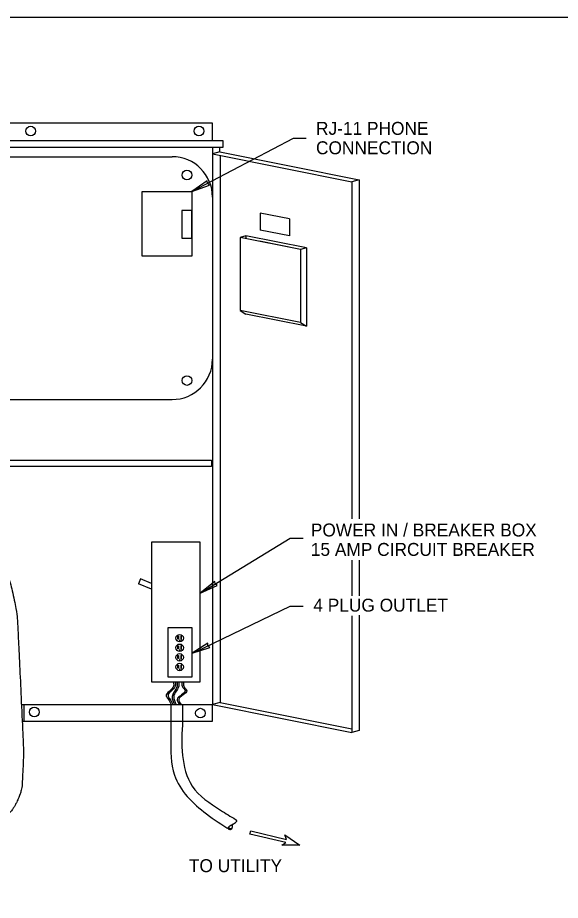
# Model space of a CAD drawing. Extents: x 99862 to 103151, y 100000 to 108076.
# Drawn here: x 100456 to 101127, y 106985 to 108076 of the extents above; entities that cross this region are included whole.
import ezdxf

# ---------------------------------------------------------------- set-up
doc = ezdxf.new("R2010")
doc.units = 0
for name, color, linetype in [('Level 1', 7, 'Continuous'), ('Level 15', 7, 'Continuous'), ('Level 20', 7, 'Continuous'), ('Level 28', 7, 'Continuous'), ('Level 30', 7, 'Continuous'), ('Level 33', 7, 'Continuous'), ('Level 34', 7, 'Continuous'), ('Level 46', 7, 'Continuous'), ('Level 50', 7, 'Continuous'), ('Level 7', 7, 'Continuous')]:
    doc.layers.add(name, color=color, linetype=linetype)

msp = doc.modelspace()

# ---------------------------------------------------------------- linework, layer by layer
at = {"layer": 'Level 1'}
msp.add_lwpolyline([(99862, 105999.5), (103151, 105999.5), (103151, 108075.5), (99862, 108075.5)], close=True, dxfattribs=at)
msp.add_lwpolyline([(99862, 105999.5), (103151, 105999.5), (103151, 108075.5), (99862, 108075.5)], close=True, dxfattribs=at)
at = {"layer": 'Level 15'}
for p, q in [((100671.8, 107860.7), (100797.3, 107926.7)), ((100797.3, 107926.7), (100813.3, 107926.7)), ((100682.2, 107364.4), (100793.5, 107432.3)), ((100793.5, 107432.3), (100809.5, 107432.3)), ((100674.5, 107291.2), (100793.5, 107348.2)), ((100793.5, 107348.2), (100809.5, 107348.2))]:
    msp.add_line(p, q, dxfattribs=at)
for points in [[(100671.8, 107860.7), (100693.4, 107868.7), (100691.1, 107870.8), (100690.6, 107874)], [(100682.2, 107364.4), (100703.2, 107373.8), (100700.7, 107375.8), (100700.1, 107378.9)], [(100672, 107290.3), (100694, 107297.3), (100691.7, 107299.6), (100691.4, 107302.7)]]:
    msp.add_lwpolyline(points, close=True, dxfattribs=at)
at = {"layer": 'Level 28'}
msp.add_open_spline([(100264, 107670.4), (100261.9, 107670.4), (100258.7, 107670.4), (100255, 107670.4), (100253.2, 107670.4), (100252.4, 107670.4), (100251.9, 107670.4), (100251.9, 107670.4), (100251.3, 107670.4), (100250.8, 107670.3), (100248.9, 107669.6), (100247.7, 107669), (100244.9, 107667.3), (100243.2, 107666.2), (100239.5, 107663.6), (100238.1, 107662.7), (100234.2, 107659.6), (100232.3, 107657.6), (100230.4, 107654.8), (100230, 107654.2), (100229.3, 107653), (100229, 107652.4), (100228.3, 107650.8), (100227.9, 107649.6), (100227.1, 107645.7), (100227, 107642.7), (100227.8, 107636.3), (100228.6, 107632.9), (100230, 107629), (100230.4, 107628), (100231.1, 107626.2), (100231.5, 107625.3), (100232.6, 107622.6), (100233.3, 107620.8), (100235.6, 107615.9), (100237.3, 107612.9), (100240.1, 107609), (100241.1, 107607.8), (100242.7, 107606.1), (100243.3, 107605.6), (100244.1, 107604.8), (100244.6, 107604.4), (100245.3, 107603.8), (100245.7, 107603.4), (100252.1, 107597.9), (100258.5, 107593.3), (100278.8, 107580.2), (100293.7, 107572.5), (100312, 107560.2), (100315.6, 107557.6), (100320.1, 107554.1), (100321, 107553.4), (100322.8, 107551.9), (100323.6, 107551.3), (100326, 107549.3), (100327.6, 107548), (100335.8, 107541.3), (100342.3, 107535.8), (100361.7, 107519.2), (100374.3, 107507.4), (100389.3, 107491), (100392.3, 107487.6), (100398.1, 107480.6), (100400.9, 107476.9), (100409, 107465.9), (100413.8, 107458.3), (100422.5, 107442.8), (100426.3, 107434.8), (100433.2, 107418.5), (100436.2, 107410), (100444.5, 107385.4), (100449.7, 107368.7), (100454.7, 107342.5), (100455.9, 107333.6), (100456.5, 107322.3), (100456.6, 107320.3), (100456.8, 107316.1), (100457.1, 107309.8), (100459, 107269.8), (100460.8, 107231.9), (100463.1, 107181.5), (100463.9, 107164.6), (100461.9, 107128.9), (100461.9, 107128.1), (100461.6, 107124.1), (100460.9, 107121.1), (100459.3, 107115.7), (100458.3, 107113.3), (100456.3, 107108.7), (100455.4, 107106.6), (100453.1, 107102.1), (100451.7, 107099.7), (100449.1, 107096), (100448.1, 107094.8), (100446.5, 107093.1), (100446.2, 107092.8), (100445.5, 107092), (100425.6, 107067), (100402.2, 107042), (100378.5, 107016.5)], degree=3, dxfattribs=at)
at = {"layer": 'Level 30'}
msp.add_lwpolyline([(100721.6, 107074.1), (100721.2, 107073.5)], dxfattribs=at)
for points in [[(100720.9, 107073), (100720.8, 107072.8), (100720.6, 107072.5), (100720.2, 107072.3), (100719.7, 107072.1), (100719.3, 107072), (100719, 107072), (100718.6, 107072.1), (100718.3, 107072.2), (100718, 107072.3), (100717.7, 107072.5), (100717.4, 107072.7), (100717.2, 107073), (100717.1, 107073.3), (100717, 107073.7), (100716.9, 107074.1), (100717, 107074.5), (100717.2, 107075), (100717.6, 107075.5), (100718, 107076), (100718.5, 107076.5), (100719.1, 107076.9), (100719.7, 107077.3), (100720.3, 107077.7), (100720.9, 107078), (100721.5, 107078.4), (100722.1, 107078.7), (100722.7, 107079), (100723.3, 107079.3), (100723.9, 107079.7), (100724.5, 107080), (100725.1, 107080.4), (100725.7, 107080.7), (100726.2, 107081.2), (100726.4, 107081.5), (100726.5, 107081.7)], [(100725.8, 107084.7), (100725.8, 107084.7), (100726, 107084.6), (100726.2, 107084.4), (100726.4, 107084.1), (100726.6, 107083.8), (100726.8, 107083.5), (100726.9, 107083.1), (100726.9, 107082.7), (100726.8, 107082.2), (100726.7, 107081.8), (100726.5, 107081.7)], [(100721.2, 107073.5), (100720.9, 107073.3), (100720.7, 107073.2), (100720.4, 107073.1), (100720, 107073.1), (100719.7, 107073.1), (100719.3, 107073.2), (100719, 107073.3), (100718.7, 107073.5), (100718.4, 107073.6), (100718.2, 107073.9), (100717.9, 107074.1), (100717.8, 107074.4), (100717.6, 107074.7), (100717.6, 107075), (100717.6, 107075.4), (100717.7, 107075.6), (100717.7, 107075.7)], [(100721.6, 107074.1), (100721.7, 107074.2), (100721.7, 107074.4), (100721.8, 107074.6), (100721.8, 107074.6)], [(100721.9, 107076.9), (100721.9, 107077.1), (100721.9, 107077.4), (100721.8, 107078), (100721.8, 107078.4), (100721.7, 107078.6), (100721.7, 107078.6)], [(100721.8, 107074.6), (100721.8, 107074.6), (100721.9, 107074.8), (100721.9, 107075.2), (100721.9, 107075.6), (100721.9, 107075.8), (100721.9, 107075.8)], [(100721.9, 107075.8), (100722, 107075.8), (100722, 107076), (100722, 107076.4), (100721.9, 107076.8), (100721.9, 107077), (100721.9, 107077)]]:
    msp.add_open_spline(points, degree=3, dxfattribs=at)
at = {"layer": 'Level 33'}
for p, q in [((100464.1, 107226.7), (100464.1, 107206.2)), ((100645.8, 107226.7), (100645.8, 107206.3)), ((100660.3, 107226.7), (100660.3, 107206.3))]:
    msp.add_line(p, q, dxfattribs=at)
at = {"layer": 'Level 34'}
msp.add_lwpolyline([(100721.2, 107073.5), (100720.9, 107073)], dxfattribs=at)
for points in [[(100649.1, 107254.6), (100649.1, 107249.5), (100640.2, 107237.1), (100642.9, 107233.1), (100645.8, 107226.9)], [(100651.2, 107254.6), (100651.2, 107249.5), (100642.3, 107237.1), (100645, 107233.1), (100647.9, 107226.9)], [(100653.6, 107254.6), (100653.6, 107249.5), (100649.4, 107241.8), (100647.4, 107236.6), (100650.4, 107226.9)], [(100655.6, 107254.6), (100655.6, 107249.5), (100651.4, 107241.8), (100649.4, 107236.6), (100652.4, 107226.9)], [(100659.7, 107254.6), (100659.7, 107249.5), (100663.5, 107243.7), (100653.5, 107233.1), (100656.5, 107226.9)], [(100661.7, 107254.6), (100661.7, 107249.5), (100665.5, 107243.7), (100655.5, 107233.1), (100658.5, 107226.9)], [(100645.8, 107206.3), (100645.8, 107184.9), (100650.2, 107139.6), (100689.9, 107091.5), (100718.6, 107072.2)], [(100660.3, 107206.3), (100660.3, 107163.8), (100672.2, 107126), (100707.3, 107096.2), (100725.8, 107084.7)]]:
    msp.add_spline(points, degree=3, dxfattribs=at)
at = {"layer": 'Level 46'}
msp.add_lwpolyline([(100743.5, 107066.7), (100744.6, 107070.5), (100788.9, 107060.1), (100786.9, 107065.6), (100805.4, 107053), (100783, 107052.9), (100787.8, 107056.3), (100743.5, 107066.7)], dxfattribs=at)
at = {"layer": 'Level 50'}
for p, q in [((100626.7, 107945), (100239.6, 107945)), ((100697.2, 107945), (100626.7, 107945)), ((100697.2, 107923.2), (100697.2, 107945)), ((100697.3, 107915.3), (100697.3, 107226.7)), ((100706.4, 107909.6), (100697.3, 107907.2)), ((100706.4, 107909.6), (100706.4, 107915.3)), ((100706.4, 107909.6), (100878.6, 107875.1)), ((100289.4, 107903.7), (100647.3, 107903.7)), ((100697.3, 107907.2), (100869.5, 107872.7)), ((100706.9, 107905.3), (100706.9, 107229.2)), ((100878.6, 107875.1), (100869.5, 107872.7)), ((100878.6, 107875.1), (100878.6, 107456.1)), ((100869.5, 107872.7), (100869.5, 107456.1)), ((100792.5, 107826.7), (100756.2, 107834)), ((100756.2, 107834), (100756.2, 107813)), ((100792.5, 107826.7), (100792.5, 107805.8)), ((100792.5, 107805.8), (100756.2, 107813)), ((100738.6, 107805.7), (100731.4, 107803.8)), ((100806.2, 107789), (100731.4, 107803.8)), ((100731.4, 107803.8), (100731.4, 107713.7)), ((100738.6, 107805.7), (100738.6, 107802.4)), ((100813.5, 107790.9), (100738.6, 107805.7)), ((100806.2, 107789), (100755.3, 107799.1)), ((100813.5, 107790.9), (100806.2, 107789)), ((100806.2, 107789), (100806.2, 107698.9)), ((100813.5, 107790.9), (100813.5, 107694.3)), ((100813.5, 107785.7), (100813.5, 107698.4)), ((100806.2, 107698.9), (100731.4, 107713.7)), ((100731.4, 107713.7), (100738.6, 107709.1)), ((100813.5, 107694.3), (100738.6, 107709.1)), ((100806.2, 107698.9), (100813.5, 107694.3)), ((100326.2, 107603.6), (100647.3, 107603.6)), ((100869.5, 107405.1), (100869.5, 107361.2)), ((100878.6, 107405.1), (100878.6, 107361.2)), ((100608.3, 107382.2), (100605.6, 107376)), ((100621.7, 107369.1), (100605.6, 107376)), ((100622, 107376.4), (100608.3, 107382.2)), ((100869.5, 107336.3), (100869.5, 107192.2)), ((100878.6, 107337), (100878.6, 107194.6)), ((100460.7, 107226.7), (100553.2, 107226.7)), ((100551.2, 107226.7), (100659.8, 107226.7)), ((100659.7, 107226.7), (100697.3, 107226.7)), ((100706.9, 107229.2), (100697.3, 107226.7)), ((100697.3, 107226.7), (100869.5, 107192.2)), ((100697.3, 107206.2), (100697.3, 107226.7)), ((100706.9, 107229.2), (100869.5, 107196.6)), ((100461.8, 107206.2), (100552.9, 107206.2)), ((100551.2, 107206.2), (100659.8, 107206.2)), ((100659.9, 107206.2), (100697.3, 107206.2)), ((100878.6, 107194.6), (100869.5, 107192.2))]:
    msp.add_line(p, q, dxfattribs=at)
for points in [[(100710.6, 107915.3), (100710.6, 107923.2), (100226.3, 107923.2), (100226.3, 107915.3)], [(100610.4, 107860.7), (100671.8, 107860.7), (100671.8, 107780.6), (100610.4, 107780.6)], [(100671.9, 107837.4), (100659.3, 107837.4), (100659.3, 107803.1), (100671.9, 107803.1)], [(100622, 107254.6), (100682.2, 107254.6), (100682.2, 107427.3), (100622, 107427.3)]]:
    msp.add_lwpolyline(points, close=True, dxfattribs=at)
msp.add_lwpolyline([(100436.1, 107528.7), (100696, 107528.7), (100696, 107520.7), (100437, 107520.7)], dxfattribs=at)
for centre in [(100472.5, 107935.3), (100680.6, 107935.4), (100665.7, 107881), (100665.7, 107627.1), (100476.9, 107217.4), (100682.4, 107216.1)]:
    msp.add_circle(centre, 5.97, dxfattribs=at)
for centre, start, end in [((100647.3, 107853.7), 0, 90), ((100647.3, 107653.6), 270, 0)]:
    msp.add_arc(centre, 50, start, end, dxfattribs=at)
at = {"layer": 'Level 7'}
for p, q in [((100656.3, 107305.8), (100656.3, 107305)), ((100657, 107305), (100656.3, 107305)), ((100657, 107305.8), (100657, 107305)), ((100656.3, 107293.9), (100656.3, 107293.1)), ((100657, 107293.1), (100656.3, 107293.1)), ((100657, 107293.9), (100657, 107293.1)), ((100656.3, 107282), (100656.3, 107281.3)), ((100657, 107281.2), (100656.3, 107281.3)), ((100657, 107282), (100657, 107281.2)), ((100656.3, 107270.2), (100656.3, 107269.3)), ((100657, 107269.3), (100656.3, 107269.3)), ((100657, 107270.1), (100657, 107269.3))]:
    msp.add_line(p, q, dxfattribs=at)
for points in [[(100672.1, 107261.1), (100672.1, 107321.3), (100642, 107321.3), (100642, 107261.1)], [(100655.1, 107311.1), (100655.1, 107307.3), (100654.3, 107307.3), (100654.3, 107311.1)], [(100658.2, 107311.1), (100658.2, 107306.9), (100658.9, 107306.9), (100658.9, 107311.1)], [(100655.1, 107299.1), (100655.1, 107295.4), (100654.3, 107295.4), (100654.3, 107299.1)], [(100658.2, 107299.1), (100658.2, 107295.1), (100658.9, 107295.1), (100658.9, 107299.1)], [(100655.1, 107287.3), (100655.1, 107283.5), (100654.3, 107283.5), (100654.3, 107287.3)], [(100658.2, 107287.3), (100658.2, 107283.2), (100658.9, 107283.2), (100658.9, 107287.3)], [(100655.1, 107275.4), (100655.1, 107271.6), (100654.3, 107271.6), (100654.3, 107275.4)], [(100658.2, 107275.4), (100658.2, 107271.3), (100658.9, 107271.3), (100658.9, 107275.4)]]:
    msp.add_lwpolyline(points, close=True, dxfattribs=at)
for centre in [(100656.7, 107308.8), (100656.7, 107296.9), (100656.7, 107285), (100656.7, 107273.1)]:
    msp.add_circle(centre, 4.59, dxfattribs=at)
for centre in [(100656.7, 107305.8), (100656.7, 107305.8), (100656.7, 107293.9), (100656.7, 107293.9), (100656.7, 107282), (100656.7, 107282), (100656.7, 107270.1), (100656.7, 107270.1)]:
    msp.add_arc(centre, 0.374, 354.1301, 179.1569, dxfattribs=at)

# ---------------------------------------------------------------- texts
at = {"layer": 'Level 20'}
for s, p in [('RJ-11 PHONE ', (100825.3, 107930.7)), ('CONNECTION', (100825.3, 107906.7)), ('POWER IN / BREAKER BOX', (100818.9, 107434.4)), ('15 AMP CIRCUIT BREAKER', (100818.9, 107410.4)), ('4 PLUG OUTLET', (100822, 107341.5)), ('TO UTILITY', (100668.1, 107019.6))]:
    msp.add_text(s, height=16, dxfattribs=at).set_placement(p)

doc.saveas('drawing.dxf')
